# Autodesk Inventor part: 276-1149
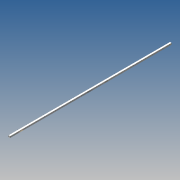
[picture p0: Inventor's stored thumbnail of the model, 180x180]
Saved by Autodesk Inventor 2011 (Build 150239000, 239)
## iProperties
Company: Autodesk Inc.
Created: 2010-06
Document SubType Name: Modeling
Designer: Autodesk Inc.
Density: 1 g/cm^3
Catalog Web Link: http://www.vexrobotics.com/shafts.html
Vendor: Innovation First, Inc.
Part Number: 276-1149
Description: The square shaft has rounded corners which allow it to spin easily in a round hole, while locking to a square hole.
Author: Autodesk Inc.
Title: VEX Robotics Kit of Parts
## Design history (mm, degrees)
sketch "Sketch1"
  geometry: L1 (0.378, 1.587)-(-0.378, 1.587); L2 (-1.334, 1.587)-(-0.378, 1.587); L3 (-1.588, 0.378)-(-1.588, -0.378); L4 (-0.378, -1.588)-(0.378, -1.588); L5 (-1.587, -1.334)-(-1.588, -0.378); L6 (-0.378, -1.588)-(-1.334, -1.587); L7 (-1.588, 0.378)-(-1.587, 1.334); L8 (1.587, 1.334)-(1.588, 0.378); L9 (0.378, 1.587)-(1.334, 1.587); L10 (1.588, -0.378)-(1.588, 0.378); L11 (1.334, -1.587)-(0.378, -1.588); L12 (1.588, -0.378)-(1.587, -1.334); A1 r 1.632 centre (0, 0) between (-0.378, 1.587) and (-1.588, 0.378); A2 r 1.632 centre (0, 0) between (-0.378, 1.587) and (-1.588, 0.378); A3 r 1.632 centre (0, 0) between (-1.588, -0.378) and (-0.378, -1.588); A4 r 1.632 centre (0, 0) between (-1.588, -0.378) and (-0.378, -1.588); A5 r 1.632 centre (0, 0) between (1.588, 0.378) and (0.378, 1.587); A6 r 1.632 centre (0, 0) between (1.588, 0.378) and (0.378, 1.587); A7 r 1.632 centre (0, 0) between (0.378, -1.588) and (1.588, -0.378); A8 r 1.632 centre (0, 0) between (0.378, -1.588) and (1.588, -0.378); 1 further point
  constraints: 24 end point, 16 point on circle, 8 centre point, 8 other
extrude "Extrusion1" new body sketch "Sketch1" distance "d0" = 304.8; taper "d1" = 0 deg
workplane "Work Plane1"
  workaxis "Work Axis1"
sketch "Sketch2"
  geometry: L1 (0, 0)-(0.352, 0); L2 (0.352, 0)-(0.352, 2.14); L3 (0.352, 2.14)-(-0.254, 2.14); L4 (0, 0)-(0, 1.39); L5 (-365.83, 0)-(61.382, 0) reference; A1 r 0.772 centre (-0.757, 1.554) between (-0.179, 2.065) and (-0.254, 2.14); 1 further point
  constraints: 8 end point, 2 perpendicular, 2 point on circle, 1 centre point, 3 other
revolve "Revolution1" sketch "Sketch2" stored, may be unused: angle "d3" = 90 deg
workplane "Work Plane2"
mirror "Mirror1"
body "Solid1"
other parameters: "d2" = 90 deg
